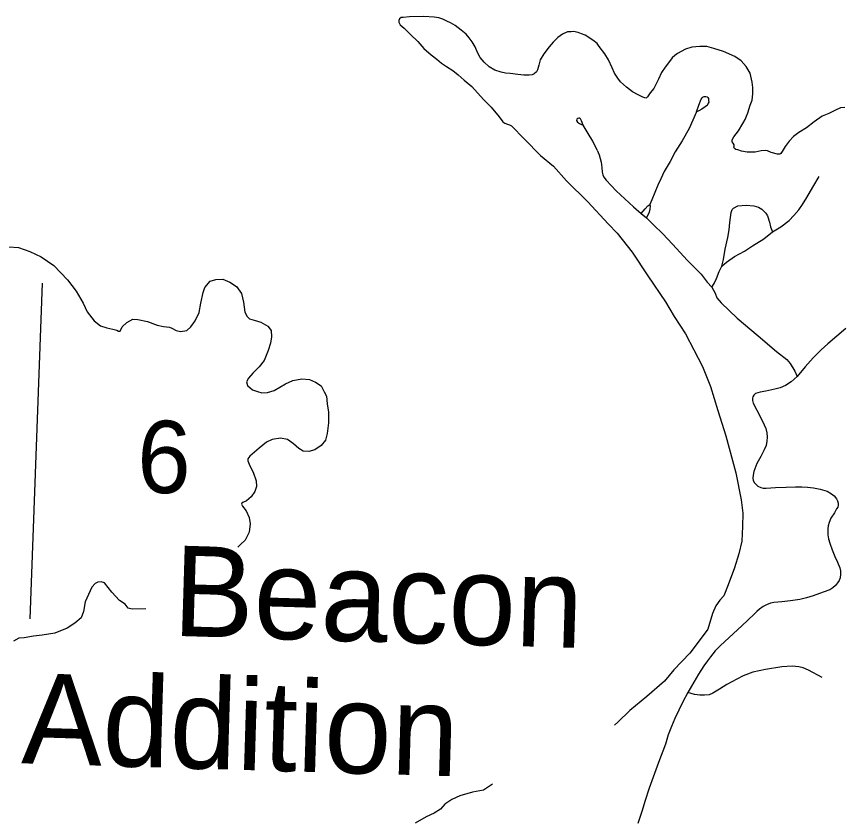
# Model space of a CAD drawing. Extents: x 653372 to 905732, y 627442 to 787275.
# Drawn here: x 720498 to 725318, y 734929 to 739622 of the extents above; entities that cross this region are included whole.
import ezdxf

# ---------------------------------------------------------------- set-up
doc = ezdxf.new("R2010")
doc.units = 0
for name, color, linetype in [('24', 7, 'Continuous'), ('31', 7, 'Continuous'), ('32', 7, 'Continuous'), ('4', 7, 'Continuous'), ('5', 7, 'Continuous'), ('9', 7, 'Continuous')]:
    doc.layers.add(name, color=color, linetype=linetype)

msp = doc.modelspace()

# ---------------------------------------------------------------- linework, layer by layer
at = {"layer": '31'}
for points in [[(724471.5, 739064.9), (724485, 739103.8), (724498.1, 739138.2), (724503.2, 739147.1), (724509.1, 739152.1), (724516.3, 739154.7), (724525.2, 739154), (724532.2, 739151.9), (724536.2, 739147.9), (724540.4, 739142.3), (724541.8, 739138.2), (724541.5, 739130.6), (724541.9, 739121.8), (724539.8, 739114.9), (724537.7, 739109.8), (724531.8, 739102), (724528.3, 739099.5), (724521.2, 739093.4), (724501.8, 739080), (724484.9, 739069.9), (724471.5, 739064.9)], [(724471.5, 739064.9), (724427.3, 738967), (724387.1, 738896.4), (724346.3, 738830.4), (724316.2, 738774.7), (724282.7, 738716.2), (724262.7, 738672.9), (724244.1, 738636.6), (724227.3, 738593.1), (724210.7, 738550.4), (724198.3, 738523.6)], [(723891.4, 738841.6), (723901.8, 738813.2), (723914.8, 738770.4), (723918.2, 738740.1), (723920, 738713.2), (723922.9, 738697.6), (723929.4, 738682.7), (723942.4, 738665.1), (724001, 738602.8), (724102.8, 738509.9), (724148.2, 738470.1), (724179.3, 738444.7), (724221.4, 738401.7), (724274.3, 738351.2), (724330.4, 738291.6), (724417.9, 738195.7), (724497.5, 738115.6), (724533.3, 738070.4), (724560.1, 738041.1), (724579.8, 738005.9), (724589.9, 737978.7), (724615.2, 737949.7), (724708.2, 737859.3), (724831.2, 737755.4), (724937.3, 737664.1), (724998.1, 737618.2), (725017.3, 737594.2), (725044.4, 737549.4), (725058, 737519)], [(724619.5, 738163.7), (724645.3, 738186.7), (724693.2, 738219.5), (724750.7, 738250.6), (724798.5, 738282.8), (724863.3, 738322.1), (724915.6, 738363.2), (724963.3, 738392.5), (725011.3, 738430.2), (725039.4, 738459.5), (725069.1, 738492.1), (725090.3, 738522.6), (725115.3, 738564.5), (725150, 738625), (725186.8, 738686.9)], [(724148.2, 738470.1), (724171.7, 738498.5), (724187, 738514.9), (724198.3, 738523.6), (724200.6, 738515.1), (724198.8, 738497.1), (724193.7, 738478.5), (724179.3, 738444.7)], [(724560.1, 738041.1), (724573.7, 738060.9), (724587.2, 738091.2), (724603.9, 738132.7), (724619.5, 738163.7), (724628.3, 738201.2), (724637.8, 738261.8), (724653.1, 738329.8), (724662.2, 738375.7), (724664.8, 738417.6), (724672.9, 738476.1), (724678.3, 738493.4), (724687, 738502.9), (724712.5, 738515.4), (724761.6, 738519.6), (724806.2, 738514.7), (724832.5, 738506.9), (724851.8, 738496.6), (724875.5, 738472.1), (724884.9, 738457.8), (724897.7, 738420.4), (724903.9, 738392.9), (724915.6, 738363.2)], [(725343.6, 737798), (725238.2, 737709.8), (725199.7, 737674.6), (725152.1, 737627.6), (725106.4, 737574.6), (725058, 737519), (725024.5, 737486.9), (724990.1, 737465.1), (724959.3, 737452.4), (724927.6, 737445.2), (724876.7, 737433.2), (724842.3, 737426.7), (724815.5, 737418.3), (724805.4, 737409.9), (724799.1, 737399.7), (724797.8, 737391.1), (724798.5, 737378), (724802.4, 737363.2), (724823.4, 737321.3), (724857.3, 737256.6), (724875.6, 737214.6), (724882.5, 737188.3), (724883.3, 737163.3), (724881.6, 737140.5), (724877, 737115.6), (724865.9, 737088.8), (724846.8, 737050.7), (724823.8, 737009), (724810.9, 736978.4), (724805.6, 736963.9), (724801.1, 736941.8), (724800.1, 736924.5), (724802.4, 736909.7), (724809, 736897), (724818.5, 736886.4), (724829.6, 736877.4), (724845.7, 736869.8), (724860.3, 736866.1), (724877.1, 736866.1), (724931.6, 736868.9), (724994.7, 736872.4)], [(724994.7, 736872.4), (725049.1, 736874), (725085.5, 736873.5), (725118.6, 736871.9), (725154.3, 736867.1), (725192.3, 736859.6), (725233.8, 736847.5), (725259.4, 736832.1), (725274.8, 736820.2), (725288.5, 736803.5), (725293.5, 736791.9), (725298, 736778.2), (725298.2, 736765.6), (725295.7, 736754.9), (725288.3, 736745.3), (725276.2, 736722.3), (725256.2, 736689.7), (725245.7, 736665), (725240.8, 736645.6), (725238.1, 736628.8), (725237.4, 736606), (725237.5, 736592.4), (725241.8, 736570.5), (725249.2, 736544.8), (725262.7, 736505.8), (725279.4, 736466.7), (725295.3, 736433.3), (725308.4, 736400.2), (725311.1, 736382.8), (725311.6, 736362.6), (725309.4, 736342.6), (725304, 736326.4), (725294.3, 736312), (725282, 736297.7), (725267.4, 736284), (725249.1, 736272.1), (725211.3, 736257.1), (725152, 736236.6), (725112.5, 736224.2), (725073.7, 736216.1), (725020.7, 736207.4), (724969.5, 736202.4), (724922, 736197.3), (724903.4, 736192.9), (724879.2, 736183.9), (724859.9, 736174.1), (724839.4, 736159), (724823.2, 736145.9), (724808, 736128.9), (724735.9, 736061), (724661, 735993.6), (724609, 735945.2)], [(724609, 735945.2), (724579.9, 735914.5), (724551.6, 735880), (724534.1, 735857.2), (724514.2, 735828), (724482.3, 735778.4), (724440.6, 735709.6), (724420.7, 735672.5), (724391.3, 735617.9), (724367, 735568.1), (724344.4, 735519.9), (724323.9, 735472.1), (724305.6, 735423.7), (724288.8, 735369.3), (724249.7, 735262.8), (724217.8, 735177.3), (724194.1, 735112.8), (724168.9, 735034.7), (724153.2, 734981.9), (724140.6, 734940.4), (724127.6, 734905.6)], [(725204.3, 735758.7), (725124.5, 735803), (725094.8, 735815.8), (725069.1, 735822.2), (725030.1, 735826.1), (724968.5, 735822.4), (724873.6, 735806.4), (724800.4, 735789.7), (724742.5, 735769.7), (724706.3, 735750.5), (724648.7, 735718.7), (724604.7, 735691.4), (724565.6, 735667.4), (724544.3, 735658.9), (724517.7, 735656.2), (724490.4, 735655.6), (724459.1, 735660.8), (724420.7, 735672.5)]]:
    msp.add_lwpolyline(points, dxfattribs=at)
at = {"layer": '32'}
for points in [[(723809.5, 738986.6), (723799.9, 739011.9), (723792.5, 739023.8), (723788.3, 739027.4), (723783.2, 739028.4), (723776.6, 739026.9), (723771.3, 739022.3), (723770.2, 739015), (723776.4, 739004.4), (723786.5, 738997.6), (723795.5, 738992.6), (723809.5, 738986.6)], [(723891.4, 738841.6), (723865.5, 738894.2), (723837.5, 738937.8), (723809.5, 738986.6)]]:
    msp.add_lwpolyline(points, dxfattribs=at)
at = {"layer": '4'}
msp.add_lwpolyline([(720648.2, 738064), (720576.1, 736102.2)], dxfattribs=at)
at = {"layer": '9'}
for points in [[(723159.9, 739474.5), (723142.4, 739497.5), (723125, 739519.7), (723095.3, 739542.4), (723061.3, 739568.8), (723033.5, 739584.8), (723011.4, 739594.9), (722988.5, 739605.7), (722964.9, 739613.7), (722939, 739617.4), (722877.6, 739622.1), (722793.5, 739621), (722757.2, 739617), (722744.9, 739615.9), (722736, 739609), (722732.8, 739599.6), (722731, 739588.1), (722739.3, 739574.1), (722762.6, 739553.8), (722800.5, 739516.4), (722842.1, 739476.8), (722878.5, 739435.1), (722921.6, 739397.6), (722954.1, 739372), (722981.7, 739348.7), (723010.8, 739330.4), (723047.1, 739306.9), (723078.2, 739282), (723114.2, 739250.5), (723158.7, 739212.2), (723227.4, 739136.3), (723270.8, 739093), (723318.3, 739035), (723339.1, 739006.2), (723350.5, 738998.6), (723367, 738993.7), (723378.5, 738989.8), (723390.6, 738982.2)], [(724307.2, 739350.8), (724288.4, 739326.8), (724266.4, 739295.6), (724248.6, 739256.2), (724221.6, 739201.3), (724200.6, 739175.9), (724185.4, 739152.4), (724177.9, 739146.1), (724174.3, 739144.8), (724156.4, 739151.1), (724129.2, 739165), (724096.4, 739181.2), (724062.5, 739208.3), (724026.5, 739241.2), (724011.2, 739261.3), (723992.5, 739290.1), (723977.5, 739322.4), (723957.2, 739368), (723934.3, 739403.4), (723902.3, 739447.1), (723889.8, 739464.2), (723865.7, 739483), (723820.2, 739512.6), (723799.5, 739521.2), (723778.7, 739529.1), (723752.8, 739533.5), (723739, 739531.7), (723717.5, 739531.7), (723687.5, 739519.5), (723660.8, 739498.6), (723633.9, 739471.9), (723609.9, 739445), (723579, 739404), (723558.3, 739368.3), (723550.2, 739337.4), (723542.8, 739310.1), (723535.2, 739298.7), (723521.9, 739287.6), (723511.5, 739280.6), (723493.4, 739279.7), (723462.9, 739279.2), (723426.8, 739283.2), (723382.8, 739288.1), (723355.4, 739291.8), (723330.2, 739297.7), (723292.7, 739309.4), (723260.5, 739327.3), (723230.2, 739355), (723206.3, 739381.8), (723192, 739411.9), (723178.5, 739445), (723159.9, 739474.5)], [(725158.6, 739006.6), (725113.6, 738971.7), (725067.9, 738943.4), (725037.5, 738921.1), (725012.8, 738894.3), (724988.7, 738862.4), (724971.1, 738832.5), (724963.5, 738821.1), (724956.9, 738818.4), (724943.1, 738817.4), (724907.9, 738827.2), (724885, 738836.5), (724871.3, 738838.4), (724849.5, 738836.2), (724813.1, 738829.3), (724767.5, 738829.2), (724732.9, 738835.3), (724711.4, 738843.2), (724700.6, 738845), (724692.8, 738851), (724687.9, 738857.7), (724690.3, 738864.1), (724690.5, 738872.1), (724684.3, 738881), (724678.7, 738889.1), (724679.8, 738901.4), (724688.3, 738918.5), (724716.2, 738953.9), (724741.4, 738997.4), (724755.1, 739020.9), (724771.5, 739059.5), (724783.7, 739104.8), (724796.9, 739134.1), (724800.1, 739169.5), (724800.5, 739206.4), (724796.4, 739239.2), (724783.5, 739290.2), (724760.8, 739330.7), (724732.1, 739363.5), (724695.1, 739387.7), (724627.9, 739416.6), (724572.7, 739435.6), (724530.3, 739446.3), (724489.7, 739446.8), (724443.3, 739443.1), (724406.7, 739431.2), (724360.3, 739405.8), (724343.3, 739394), (724328.4, 739380.6), (724307.2, 739350.8)], [(725337, 739090.3), (725311.6, 739087.5), (725283.7, 739074.6), (725243.3, 739055.5), (725205.2, 739039.2), (725158.6, 739006.6)], [(723390.6, 738982.2), (723465.6, 738905), (723560, 738810.4), (723634.9, 738748.3), (723710.8, 738661.8), (723836.2, 738538.3), (723954, 738411.2), (724006.6, 738355.4), (724094.9, 738244.2), (724186.2, 738106.7), (724290.1, 737953.9), (724339.9, 737868.2), (724406.1, 737767), (724455.7, 737673.8), (724506.6, 737576.4), (724551.7, 737459), (724596.2, 737319.2), (724642.3, 737171.9), (724701.2, 736954.9), (724732, 736796.8), (724740.9, 736719.8), (724738.6, 736641.3), (724736, 736555.3), (724718.9, 736482.8), (724692, 736399.4), (724655.4, 736300.9), (724631, 736236.2), (724607.8, 736210.7), (724584.3, 736177.7), (724564.3, 736133.4), (724537.3, 736042.5), (724509.9, 736004), (724432, 735901.5), (724337.4, 735803.3), (724283, 735737.6), (724181.2, 735649), (724081.4, 735565.9), (724012.1, 735498.7), (723991, 735480.5)], [(720454.4, 738276.8), (720509.8, 738272.4), (720575.7, 738249.6), (720642.7, 738218.4), (720716, 738166.3), (720796.7, 738083.4), (720847.4, 738016.7), (720887, 737947.5), (720910.4, 737896.9), (720952.4, 737844.3), (720988.9, 737814), (721026, 737801.8), (721060.5, 737795.2), (721085.2, 737788.9), (721093.4, 737783.2), (721103.1, 737782.9), (721116.3, 737808.8), (721143.4, 737833), (721178.7, 737852.7), (721206.4, 737851.9), (721264.3, 737839.1), (721320.5, 737818), (721356.4, 737811.3), (721392.3, 737806.1)], [(721392.3, 737806.1), (721405.9, 737800.1), (721431.9, 737786.9), (721456.7, 737782), (721493, 737787.8), (721517.1, 737807.9), (721541.8, 737843.2), (721565.4, 737892.5), (721575.4, 737946.3), (721589.7, 738008.3), (721598.9, 738038.5), (721630.6, 738075), (721662.8, 738085.1), (721703, 738086.7), (721744.1, 738068.8), (721783.6, 738044.1), (721812.8, 738002.9), (721825.2, 737952.6), (721831.8, 737894.2), (721844.9, 737868.8), (721859.7, 737854.5), (721887.2, 737846.7), (721926.4, 737835.8), (721965.9, 737812.4), (721986, 737786.9), (721987.6, 737749.4), (721982.4, 737713.5), (721968.6, 737669.5), (721944.6, 737611.9), (721915.8, 737573.9), (721878.6, 737537.6), (721852.8, 737509.2), (721841.1, 737487.4), (721848.7, 737466.4), (721877.1, 737440.5), (721905.9, 737430), (721932, 737422.2), (721965.4, 737425.4), (722003.2, 737436.7), (722069.6, 737476.4), (722113.1, 737495.9), (722166.1, 737505.4), (722210.4, 737501.3), (722246, 737485), (722277.2, 737463.2), (722295.6, 737428), (722308.7, 737402.6), (722312.9, 737359.5), (722321.1, 737309.3), (722320.7, 737248.3), (722313.2, 737185.5), (722303.8, 737146.9)], [(722303.8, 737146.9), (722277.9, 737115.8), (722241, 737089.1), (722206, 737079.1), (722172.9, 737082.9), (722146.9, 737097.5), (722115.9, 737124.8), (722081.9, 737149.4), (722040.6, 737157.6), (721991.8, 737149.3), (721959.5, 737135.1), (721915.4, 737098.9), (721862.1, 737052.8), (721850.5, 737036.5), (721849.4, 737026), (721861, 736996.5), (721880.6, 736958.5), (721898.6, 736909.4), (721900.4, 736876), (721891.1, 736845.8), (721869.4, 736814.5), (721842.4, 736791.7), (721821.3, 736782.7), (721815.7, 736782.8), (721812.6, 736771.8), (721818.5, 736761.1), (721839.9, 736734.1), (721857.5, 736694.2), (721863.3, 736657.9), (721856.7, 736609.1)], [(721856.7, 736609.1), (721834.5, 736562.6), (721806, 736535.7), (721791.3, 736521.4)], [(721254.2, 736160.1), (721174.7, 736157.9), (721151.3, 736164.2), (721134, 736188.3), (721099.9, 736208.7), (721055.7, 736258.6), (721012.9, 736312.6), (720992.3, 736318.8), (720972.8, 736316.6), (720958.7, 736308.7), (720938.6, 736287.1), (720919.6, 736244.6), (720900.2, 736200.8), (720890.3, 736145.6), (720876.6, 736107.2), (720839.7, 736077.8), (720794.4, 736047.2), (720722.8, 736017.5), (720647.6, 736007.3), (720597.5, 736001.8), (720543.1, 735991), (720511.1, 735989.2), (720480.1, 735972.1)], [(723278.4, 735135.5), (723266.7, 735127.4), (723226.6, 735100.5), (723162.6, 735089.3), (723089, 735067.2), (723041.6, 735046.2), (723001.5, 735019.3), (722974.4, 734990.2), (722938.2, 734966.9), (722890.8, 734945.9), (722827.9, 734908.5)]]:
    msp.add_lwpolyline(points, dxfattribs=at)

# ---------------------------------------------------------------- texts
at = {"layer": '24'}
for s, p in [('Beacon', (721407.5, 736003.2)), ('Addition', (720524.4, 735258.1))]:
    msp.add_text(s, height=528, rotation=358.28, dxfattribs=at).set_placement(p)
at = {"layer": '5'}
msp.add_text('6', height=422.4, rotation=358.28, dxfattribs=at).set_placement((721197.6, 736842.2))

doc.saveas('drawing.dxf')
